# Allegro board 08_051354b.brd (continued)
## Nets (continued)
UNNAMED_12_DIOLED_I181_P: DS4.A(P) R37.1
UNNAMED_12_DIOLED_I182_N: DS5.C Q2.3
UNNAMED_12_DIOLED_I182_P: DS5.A(P) R75.2(N2)
UNNAMED_12_ICFSA642_I1_OEN: R90.2(N2) U7.8
UNNAMED_12_ICFSA642_I1_SEL: S1.2 U7.11
UNNAMED_12_ICPCA9517A_I144_EN: R101.1 U8.5
UNNAMED_12_ICPCA9517A_I145_EN: R24.2(N2) U9.5
UNNAMED_12_RES_I54_N1: R91.1 S1.1(NO)
UNNAMED_12_RES_I55_N2: R36.2(N2) S1.3
UNNAMED_12_RES_I155_N2: R77.2(N2) S3.1
UNNAMED_12_RES_I158_N2: R80.2(N2) S4.2(B)
UNNAMED_12_RES_I178_N2: Q2.2 R78.2(N2)
UNNAMED_12_RES_I179_N2: Q2.5 R79.2(N2)
VD: TP1.1(N1) U4.F1
VL: R10.1 R53.2(N2) R70.2(N2)
VL_AFE: C20.2(N2) C27.1 R10.2(N2) U4.K11(VL)
VLD: P21.2 P21.4 P21.6 P21.8 P21.10 P21.12 P21.14 P21.16 P21.18(N9) P21.20 P21.22 P21.24 R11.1 R39.1 R108.2(N2)
VSUB: C44.1 C55.1 C64.1 JP2.1 JP9.1 R8.2(N2) R56.1 U6.1 U6.8(VDD2)

Pads without a net: P1 11 12 16 17 18 19 20 21 22 23 24 25 26 27 28 29 30; P3 2 3 4 5 8 10 14 15 16 17 20 21 22 23 26 27 28 29 33 35 36 38 39 41 45 47 51 53 57 59 60; P4 3 4 5 6 7 9 11 12 13 14 16 18 20 22 30 31 32 33 34 35 36 37 38; P21 17 19 21 23 25 26 28 41 43 45 47 49 51 53 55 57 59; S2 3; U1 1 7 10 12 25 26 31 32 34 38; U2 B1 C1; U3 6; U4 D4 D5 E5 F6 F7 F8 F9 G6 G7 H6 K5 K9 L2 L3 L9; U5 1; U7 7 24; U10 3 4 8

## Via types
v1: diameter 0.508, hole 0.254, TOP to BOTTOM, 340 vias
v2: diameter 0.254, hole 0.127, TOP to L2_GND, 76 vias
v3: diameter 0.457, hole 0.203, TOP to BOTTOM, 3 vias
v4: diameter 0.254, hole 0.127, L2_GND to L3_SIG, 35 vias
v5: diameter 0.635, hole 0.305, TOP to BOTTOM, 245 vias
v6: diameter 0.254, hole 0.127, L9_GND to BOTTOM, 8 vias

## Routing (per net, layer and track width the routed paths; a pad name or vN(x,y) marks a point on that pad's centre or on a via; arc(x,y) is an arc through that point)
5V_LD: length 1.5
  TOP w0.381: v1(16.9,32.64) 17.09,32.64 17.27,32.82 JP3.1
  vias: v1(36.32,27.18) v1(36.32,26.16) v1(37.34,26.16) v1(38.35,26.16) v1(39.37,27.18) v1(39.37,26.16) v1(50.5,23.44) v1(50.5,22.68) v1(50.47,21.92) v1(50.47,21.16) v5(7.49,23.37) v5(7.49,22.35) v5(7.49,21.34) v5(8.51,21.34) v5(8.64,23.38) v5(9.53,23.38) v5(14.73,31.95) v5(14.69,30.99) v5(14.69,30.1) v5(15.62,31.98)
5VCC: length 15.1
  TOP w0.508: R37.2 v1(38.95,10.29) ; R75.1 v1(42.63,10.25)
  BOTTOM w0.508: JP6.1 v5(31.23,25.76) 32.86,25.76 33.37,25.25 JP8.1 ; v1(5.58,30.86) 5.58,30.81 5.57,30.79 E2.2 5.57,27.14 E3.1 2.62,27.01 C49.2
  BOTTOM w0.584: JP7.1 22.45,23.02
  vias: v1(22.4,19.56) v1(22.43,18.8) v1(23.11,19.56) v1(23.11,18.8) v5(22.02,22.99) v5(22.83,22.99)
9VDD: length 131.2
  TOP w0.127: 77.92,25.43 U4.K10
  TOP w0.305: C15.1 79.72,25.56 79.46,25.83 78.32,25.83 77.92,25.43
  TOP w0.508: R9.1 v5(115.87,21.34) ; v1(82.21,24.28) 82.21,24.65 C12.1 81.22,25.52 80.36,25.52 C15.1
  L8_SIG w0.305: v1(95.83,7.75) v1(95.07,7.75) 92.82,7.75 90.53,10.03 80.14,10.03 77.98,7.87 75.06,7.87 73.53,6.35 61.09,6.35 57.78,3.05 52.83,3.05 47.75,8.13 42.06,8.13 40.26,9.93 40.26,11.62 27.99,23.89 27.99,32.69 29.08,33.78 29.08,41.66 28.32,42.42 15.33,42.42 v1(10.76,37.85)
  BOTTOM w0.203: R26.1 110.81,26.99 110.54,26.72 Q1.4
  BOTTOM w0.254: R26.1 v5(112.27,26.99)
  BOTTOM w0.508: R104.1 v1(10.76,37.85) ; R71.2 v5(93.82,24.38)
GND: length 259
  TOP w0.127: v2(78.45,20.26) 78.15,20.56 77.75,20.56 v2(77.4,20.91)
  TOP w0.165: U4.D6 v2(73.9,23.41)
  TOP w0.203: v5(100.98,11.68) 101.54,11.12 U12.C2
  TOP w0.254: 83.05,38.29 U8.4 ; v1(109.47,22.48) A1.2 A1.PAD ; U4.B7 v2(73.9,23.41) ; 82.29,9.01 C69.1 81.55,9.71 ; P21.42 59.49,20.17 ; P21.38 59.38,21.17 59.46,21.25 ; 59.65,16.09 59.46,16.09 59.39,16.16 P21.58 ; 15.73,38.32 Q2.1 15.12,37.66 ; P21.34 59.47,22.17 ; U4.B3 v2(73.9,21.41) ; C68.2 90.56,42.01 ; 17.03,40.22 Q2.4 17.03,38.9 ; P21.54 59.47,17.17 ; 79.92,15.35 C77.1 79.02,14.47 ; P21.30 59.11,23.17 59.4,23.46 59.4,23.82 v1(59.78,24.2) ; C85.2 41.21,6.33 ; P1.1 48.19,15 ; 69.56,34.43 RT1.1 ; 72.35,4.6 C1.1 ; 82.46,9.27 U13.7 ; C83.1 71.55,30.3 ; U4.E2 v2(74.4,20.91) ; 81.65,42.16 C63.1 80.18,42.16 ; v2(76.9,24.91) U4.H10 v2(75.9,24.91) ; C79.2 104.03,12.89 ; v2(73.4,22.41) U4.C5 ; v2(74.9,24.41) U4.E10 U4.D10 v2(73.9,24.91) U4.C9 v2(73.4,24.41) ; 59.81,18.12 59.46,18.12 59.42,18.17 P21.50 ; P21.46 59.42,19.17 59.46,19.22 59.68,19.22
  TOP w0.305: v5(81.76,38.61) 82.06,38.9 U8.4 ; C23.2 69.39,18.66 v1(69.34,18.61) ; C84.2 v1(39.5,5.71) ; C85.2 v1(40.39,5.71) ; 12.46,43.57 DS3.C ; P21.PAD2 v5(55.05,29.08) P21.PAD1 v5(55.05,32.73) ; 26.14,18.29 25.7,18.29 25.7,18.37 25.39,18.68 U10.19 ; P21.PAD3 v5(55.05,16.76) P21.PAD4 v5(55.05,13.01) ; U10.13 20.87,21.31 ; C26.2 v1(69.35,25.7) ; v1(74.8,16.31) 74.8,16.69 C54.2 ; v1(70.96,16.8) 71.35,16.4 71.82,16.4 C53.1 ; C14.2 70.15,22.59 v1(69.92,22.35) ; C16.2 69.8,20.99 v1(69.39,20.99) ; v1(69.35,19.67) 69.36,19.65 69.37,19.65 69.41,19.62 69.41,19.62 69.48,19.55 C31.2 ; C33.2 v1(76.88,16.36) ; Q2.1 v1(15.73,36.93) ; v1(75.49,16.47) C19.2
  TOP w0.381: U1.20 99.23,19.55 v5(99.49,19.81) ; v5(97.07,25.53) 97.31,25.76 U1.29
  TOP w0.406: U1.6 v5(90.18,23.16) ; v5(99.45,21.21) U1.22 ; Q2.4 v1(18.03,39.56) ; U1.24 99.35,22.51
  TOP w0.508: C57.1 72.91,34.6 v1(72.89,34.62) ; 114.47,26.49 C29.1 v1(115.32,25.76) ; C24.2 v1(62.52,22.41) ; C69.1 v5(80.54,9.01) ; R73.1 71.77,34.42 v1(72.01,34.67) ; C11.2 78.26,29.42 v1(78.25,29.41) ; C11.2 79.17,30.3 ; C11.2 80.07,29.42 ; P1.4 48.35,18 ; C12.2 v1(84.16,25.19) ; C72.2 v5(28.72,25.15) ; C62.1 v5(113.84,20.57) 113.84,19.81 113.2,19.18 C65.2 112.56,18.44 ; v5(21.26,25.02) 21.37,25.03 22.14,25.03 C74.2 ; v5(75.15,6.32) 75.79,6.96 C56.1 ; R18.1 v5(15.01,19.77) ; R57.2 v1(95.63,8.84) ; v5(18.92,34.29) R14.2 19.82,35.07 ; P1.1 46.96,14.36 v5(47.12,14.21) ; C13.2 v1(82.68,34.92) ; C13.2 v1(84.39,33.21) ; C13.2 v1(80.64,33.21) ; JP5.2 107.57,18.54 ; C77.1 79.25,15.12 v1(79.25,14.38) ; Y1.2 62.42,24.89 v5(61.45,24.89) ; U13.7 v5(85.74,9.27) ; P31.3 14.47,9.68 ; P31.3 14.47,13.28 ; P31.3 16.08,11.48 ; P31.3 14.44,11.51 v5(12.78,11.51) ; v5(104.65,12.97) 104.65,12.31 C79.2 103.38,12.33 v5(103.38,12.97) ; C1.1 73.35,4.29 v5(72.27,4.29) ; C1.1 73.66,5.57 ; C1.1 73.66,3.62 ; v5(92.22,12.95) R103.1 91.2,13.67 ; TP18.1 42.18,42.87 v1(42.64,43.32) ; 74.27,35.66 C6.2 74.51,34.92 v1(75.31,34.92) ; C20.1 v1(84.03,26.71) ; R106.1 v5(92.2,9.41) ; 99.45,12.89 C81.2 ; C81.2 v5(100.98,11.68) ; C81.2 v5(97.87,11.68) ; v1(70.35,35.26) 70.35,35.26 70.37,35.23 RT1.1 ; C63.1 v5(80.91,43.37) ; C10.2 67.9,27.6 66.34,29.16 C61.2 v1(64.55,29.64) ; v1(48.35,20.64) 47.99,21 P1.7 ; C5.2 v1(65.31,25.38) ; v1(71.37,30.31) 71.37,29.6 C83.1 ; C68.2 v5(91.96,41.27) ; v5(16.56,6.99) 16.59,7.01 R23.2 ; v1(70.14,14.28) C7.2 ; v5(27.82,34.78) 27.78,34.78 27.36,34.81 R25.2 ; R48.2 v5(32.1,24.51) ; v1(3.29,36.7) R36.1 4.02,35.81 ; v5(48.3,23.31) 48.3,23.49 47.79,24 P1.10 ; A1.PAD v5(111.3,23.58)
  TOP w0.635: DS1.C v1(12.46,34.26) ; DS1.C 12.46,36.97 ; DS1.C 13.62,35.81 ; v1(12.46,41.25) DS3.C 13.62,42.42 ; DS2.C v1(13.72,39.12) ; DS2.C 12.46,40.27 ; DS2.C 12.46,37.96
  TOP w0.762: C82.1 84.02,21.64
  L2_GND w0.14: 74.64,24.83 74.76,24.71 74.76,24.56 v2(74.9,24.41)
  L2_GND w0.203: v1(71.74,22.19) 71.74,22.2
  L9_GND w0.203: v6(23.41,35.68) 23.41,36.53 v1(23.24,36.7)
  BOTTOM w0.203: U7.9 74.25,9.83 v5(74.55,9.53)
  BOTTOM w0.254: R63.1 48.04,15.5 ; 44.19,18.92 U5.4 44.77,17.69 ; 43.19,15.5 R54.1
  BOTTOM w0.305: 16.16,13.41 U3.14 ; U3.5 21.81,13.41 ; U5.4 v5(44.77,20.31) ; U6.5 99.86,15.33 v5(100.23,15.7) 100.59,15.33 U6.4
  BOTTOM w0.381: JP4.3 13.62,10.67 v5(12.78,11.51) ; v5(102.54,34.54) 101.94,33.95 D6.C v5(102.79,33.53) ; U9.4 70.23,33.99 v1(69.39,34.82) ; v5(47.12,14.21) 47.12,14.23 47.27,14.38 R63.1 ; C70.1 v1(66.22,31.99)
  BOTTOM w0.508: P3.30 v5(61.89,8.73) ; C30.2 v5(109.42,30.43) ; R90.1 v5(78.66,10.11) ; R90.1 77.56,9.33 ; R90.1 77.56,10.88 ; v5(47.94,29.91) 47.94,29.19 47.9,29.15 R60.1 48.68,28.44 ; R29.2 v5(106.88,28) ; C40.2 v5(31.1,34.23) ; C40.2 v5(32.43,35.56) ; C40.2 31.1,36.77 ; 39.55,35.49 P4.1 39.55,37.66 39.24,37.97 38.23,37.97 ; P3.6 v5(52.29,8.7) ; v5(30.79,40.64) C35.2 30.01,41.38 ; 77.55,43.45 P4.40 v5(78.7,41.68) ; P3.31 v5(62.69,4.38) ; v5(104.65,12.97) 104.65,12.95 104.41,12.71 C80.2 ; v5(38.38,41.72) 38.43,41.68 P4.2 39.55,43.45 ; P3.55 72.29,4.27 v5(72.27,4.29) ; P3.52 70.69,8.97 70.71,8.99 v5(70.71,9.03) ; P3.24 v5(59.49,8.73) ; C52.2 47.67,24.09 ; R20.2 v5(18.33,6.48) ; v1(50.43,24.3) C67.1 ; C67.1 51.94,23.42 ; C67.1 52.84,24.3 ; 81.41,21.25 R2.1 80.69,22.03 ; P3.43 v5(67.49,4.29) ; C18.2 108.16,24.85 v5(108.4,25.1) ; v5(65.75,8.71) 65.89,8.58 P3.40 ; P3.19 v5(57.89,4.29) ; P3.12 v5(54.69,8.73) ; v5(77.55,35.42) P4.39 78.46,37.42 ; v5(30.01,38.52) R13.2 30.74,39.37 ; v5(73.51,8.72) 73.09,8.31 P3.58 ; JP8.3 v5(36.11,24.13) ; P3.18 v5(57.09,8.73) ; P3.37 v5(65.09,4.29) ; R38.2 103.13,12.72 v5(103.38,12.97) ; R27.2 v5(110.59,30.41) ; P3.13 55.49,3.91 v5(56.22,4.64) ; C75.2 78.76,29.87 ; P3.49 v5(69.89,4.29) ; P3.25 v5(60.29,4.29) ; C42.2 v1(9.86,32.77) ; R54.1 v5(43.96,14.1) ; P3.46 v5(68.29,8.73)
  BOTTOM w0.584: 111.36,29.61 R27.2 ; v5(48.3,23.31) 48.41,23.43 C52.2 ; 105.91,27.27 R29.2 ; 105.15,11.68 C80.2 ; C18.2 107.51,24.15 107.55,24.15 ; C76.2 v5(92.71,22.61)
  vias: v1(48.4,18.67) v1(59.82,14.99) v1(60.25,30.18) v1(60.24,28.14) v1(60.24,26.17) v1(61.34,18.92) v1(61.47,16.89) v1(61.72,22.23) v1(61.72,20.07) v1(61.85,14.99) v1(62.23,20.57) v1(62.61,17.78) v1(69.25,22.58) v1(72.52,28.96) v1(81.55,14.61) v1(82.01,20.77) v1(83.87,21.27) v2(72.57,28.3) v2(73.4,20.91) v2(73.9,20.91) v2(74.4,21.41) v2(74.52,28.38) v2(74.9,21.91) v2(75.9,20.91) v2(76.2,28.3) v2(76.96,28.3) v2(77.9,22.91) v2(79.36,18.08) v2(80.32,27.48) v2(80.31,24.61) v2(80.31,21.32) v5(1.65,25.53) v5(2.54,25.53) v5(3.27,22.42) v5(3.43,25.53) v5(4.25,22.86) v5(4.25,21.97) v5(5.21,23.5) v5(6.22,23.5) v5(10.16,15.62) v5(10.92,16) v5(11.43,6.48) v5(11.43,5.59) v5(11.43,4.7) v5(11.56,15.49) v5(12.19,16) v5(12.78,13.31) v5(12.78,12.45) v5(13.08,3.43) v5(14.1,3.43) v5(15.49,13.36) v5(16.18,4.06) v5(18.03,21.59) v5(18.29,14.86) v5(18.29,13.46) v5(18.92,21.59) v5(18.96,14.16) v5(19.6,14.86) v5(19.56,13.46) v5(21.72,12.19) v5(21.72,11.33) v5(22.99,31.75) v5(22.99,30.86) v5(22.99,29.97) v5(22.99,29.08) v5(22.99,28.19) v5(22.99,27.3) v5(23.88,28.96) v5(24.08,22.15) v5(24.08,21.34) v5(24.08,20.45) v5(24.6,7.18) v5(24.6,5.02) v5(24.77,28.96) v5(24.89,22.15) v5(24.89,21.34) v5(24.89,20.45) v5(25.53,4.06) v5(25.71,22.15) v5(25.71,21.34) v5(25.7,20.45) v5(26.37,4.06) v5(27.18,4.06) v5(27.99,4.06) v5(28.24,16.71) v5(28.24,15.7) v5(28.24,14.68) v5(29.89,16.71) v5(29.89,15.7) v5(40.1,35.57) v5(64.9,14.99) v5(72.14,5.33) v5(100.25,21.97) v5(100.25,16.94) v5(100.88,22.99) v5(101.65,21.34) v5(102.28,22.1) v5(103.12,30.99) v5(103.12,29.97) v5(104.14,30.99) v5(104.14,29.97) v5(106.6,20.73) v5(106.6,19.71) v5(106.6,18.69) v5(106.6,17.68) v5(106.6,16.66) v5(106.6,15.65) v5(107.53,17.73) v6(72.99,25.13) v6(73.67,25.14)
V1: length 19.5
  TOP w0.203: v1(90.1,27.41) 90.1,27.93 90.3,28.13 92.59,28.13 93.21,27.52 U1.37
  L2_GND w0.14: v4(78.53,24.94) 77.43,24.94 v2(76.9,24.41)
  L3_SIG w0.165: v4(78.53,24.94) 78.53,25.3 79.43,26.2 84.53,26.2 84.73,25.99 88.68,25.99 v1(90.1,27.41)
V2: length 16.3
  TOP w0.203: v1(88.1,24.91) 88.63,25.44 89.99,25.44 90.31,25.11 U1.3
  L2_GND w0.14: v2(76.9,23.91) 77.55,24.56 78.66,24.56 v4(79.04,24.94)
  L3_SIG w0.165: v4(79.04,24.94) 79.04,24.9 79.08,24.86 79.08,24.8 79.46,24.42 80.08,24.42 80.92,25.26 83.12,25.26 83.71,24.66 85.93,24.66 86.32,25.05 87.47,25.05 87.61,24.91 v1(88.1,24.91)
V3: length 31.8
  TOP w0.203: v1(93.32,29.66) 93.32,28.23 93.86,27.69 U1.36
  L2_GND w0.14: v1(75,30.2) 74.47,29.67 74.47,28.96 74.93,28.5 74.93,27.2 74.36,26.63 74.36,25.52 75.05,24.84 75.05,24.77 75.53,24.29 75.53,23.73 75.85,23.41 v2(76.4,23.41)
  L3_SIG w0.165: 77.81,32.07 77.79,32.05 77.77,32.05 76.76,31.03 75.84,31.03 v1(75,30.2)
  L3_SIG w0.178: v1(93.32,29.66) 92.69,29.66 90.28,32.07 77.81,32.07
V4: length 14.6
  TOP w0.203: v1(89.49,24.72) 89.75,24.46 U1.4 ; v4(79.55,24.94) 79.17,24.94 79.14,24.91 U4.L10
  L3_SIG w0.165: v1(89.49,24.72) 89.49,25.21 89.18,25.52 84.54,25.52 84.33,25.73 80.34,25.73 v4(79.55,24.94)
V9: length 18
  TOP w0.203: v1(85.3,26.5) 89.8,26.5 90.53,25.76 U1.2
  L3_SIG w0.122: 76.9,23.43 v4(76.9,23.41)
  L3_SIG w0.165: v1(85.3,26.5) 83.63,28.16 80.72,28.16 77.31,24.75 77.31,23.84 76.9,23.43
V10: length 24.2
  TOP w0.203: v1(89.96,18.41) 92.96,18.41 93.21,18.66 U1.13
  L2_GND w0.14: v2(77.4,23.91) 77.67,24.17 v4(78.53,24.17)
  L3_SIG w0.165: v1(89.96,18.41) 91.22,18.41 91.66,18.86 91.66,20.65 90.98,21.33 88.95,21.33 86.61,23.68 80.96,23.68 80.71,23.42 78.82,23.42 78.53,23.71 v4(78.53,24.17)
V11: length 21.6
  TOP w0.203: U1.14 93.86,18.4 93.23,17.78 90.61,17.78 90.58,17.75 v1(90.08,17.75)
  L3_SIG w0.165: v1(90.08,17.75) 89.55,17.75 89.2,18.1 89.2,18.79 85.73,22.26 82.75,22.26 82.45,21.96 78.65,21.96 78.04,22.57 76.56,22.57 v4(76.4,22.41)
V12: length 20.6
  TOP w0.203: v1(94.46,28.08) 94.51,28.03 U1.35 ; v1(87.31,24.35) 86.46,24.35 85.66,23.56 80.14,23.56 79.79,23.91 U4.L8
  BOTTOM w0.203: v1(94.46,28.08) 92.23,28.08 90.59,26.45 88.18,26.45 87.31,25.57 v1(87.31,24.35)
V13: length 16
  TOP w0.203: v1(90.12,22.19) 90.45,21.86 U1.8
  L2_GND w0.14: v4(79.04,24.17) 78.66,23.79 77.78,23.79 v2(77.4,23.41)
  L3_SIG w0.165: v4(79.04,24.17) 79.32,23.89 80.3,23.89 81.2,24.79 82.69,24.79 83.33,24.15 86.8,24.15 88.76,22.19 v1(90.12,22.19)
V14: length 16.2
  TOP w0.203: v1(90.34,19.81) 90.6,19.55 U1.11
  L3_SIG w0.165: v1(90.34,19.81) 89.09,19.81 86.17,22.74 81.66,22.74 81.36,22.43 78.85,22.43 78.37,22.91 v4(76.9,22.91)
V15: length 16
  TOP w0.203: v1(90.31,20.57) 90.31,21.01 90.51,21.21 U1.9
  L2_GND w0.14: v2(77.4,22.91) 77.78,23.29 78.66,23.29 v4(79.04,22.9)
  L3_SIG w0.165: v4(79.04,22.9) 80.93,22.9 81.23,23.21 86.42,23.21 89.05,20.57 v1(90.31,20.57)
V16: length 13.9
  TOP w0.203: U1.5 88.27,23.81 87.5,23.05 80,23.05 79.64,23.41 U4.L7
1P8VDD: length 42.1
  TOP w0.203: 72.51,26.6 72.51,26.3 U4.B11 ; U4.L5 78.27,22.41 ; U4.K1 77.61,20.2 ; U4.A6 72.34,22.91 72.03,23.22 ; 76.4,25.8 U4.H11
  TOP w0.254: U4.B6 U4.A6
  TOP w0.305: C28.1 72.51,27.68 71.69,27.68 ; 78.27,22.41 78.72,21.95 C22.1 80.95,21.95 81.26,21.64 C82.2 ; 76.4,25.8 76.4,26.23 76.96,26.79 v1(76.96,27.1) C17.1 ; U4.E1 74.9,19.3 v1(75.49,18.71) C19.1 ; 77.61,20.2 78.72,19.09 C25.1 78.72,17.3 79.04,16.98 ; U4.B1 73.36,20.36 73.07,20.36 71.37,18.66 71.3,18.66 v1(71.23,18.59) 71.16,18.66 C23.1 ; v1(68.43,22.53) 68.43,22.59 69.05,23.22 C14.1 72.03,23.22
  TOP w0.381: v1(81.23,20.53) 81.25,20.53 81.25,21.57 C82.2 ; 72.51,26.6 C28.1
  TOP w0.508: R72.2 68.44,34.24 v5(68.44,34.51) ; E1.2 66.57,24.36 66.58,24.35 v5(66.58,24.32) ; v1(73.03,31.56) 73.76,31.56 74.27,32.06 C6.1 ; 71.69,27.68 C83.2 70.48,28.88 v1(70.48,29.08) ; C77.2 79.08,17.01 v1(80.02,17.01) ; v5(84.88,17.09) JP1.1
  L3_SIG w0.203: 75.43,20.94 75.63,21.14 75.63,21.14 v4(75.9,21.41)
  L3_SIG w0.305: v1(75.49,18.71) 75.09,19.11 75.09,20.58 75.43,20.92 75.43,20.94
  BOTTOM w0.508: D4.A 92.44,19.43 91.31,18.3 v5(91.31,17.02)
  vias: v5(15.53,22.67) v5(15.58,23.69) v5(16.47,23.69)
2P1VDD: length 1.9
  BOTTOM w0.254: U3.21 18.71,17.64 v1(18.97,17.91)
  vias: v5(17.65,5.21) v5(17.65,4.06) v5(18.67,4.06)
3P3VDD: length 64.9
  TOP w0.203: U4.A10 72.73,24.91 72.54,25.1 72.19,25.1 ; 74.34,19.73 74.4,19.79 U4.D1 ; U4.A4 72.42,21.91 71.92,21.41 ; 72.61,20.62 U4.A2 ; 76.96,26.01 76.9,25.95 U4.J11 ; U4.D11 74.4,25.83 74.76,25.83 74.9,25.69 U4.E11 ; U4.G11 75.9,25.92
  TOP w0.229: 77.21,7.35 E5.1
  TOP w0.254: v1(50.62,28.17) 50.8,28.17 50.8,28.17 P21.9
  TOP w0.305: C68.1 89.13,40.85 U8.8 ; C58.1 v1(76.2,27.1) 76.2,26.79 75.9,26.49 75.9,25.92 ; 72.61,20.62 71.64,19.65 v1(71.23,19.65) ; 74.34,19.73 74.34,18.99 v1(74.6,18.73) ; U4.A8 72.61,23.91 72.42,24.11 72.41,24.11 72.26,24.26 71.69,24.26 v1(71.29,24.66) ; 76.96,26.01 77.85,26.9 77.85,26.92 ; 74.4,25.83 74.25,25.99 74.25,27.03 74.52,27.3 C60.1 74.23,27.74 v1(73.93,28.05) ; C16.1 70.65,20.77 71.13,20.77 71.18,20.72 71.19,20.72 v1(71.21,20.7) 71.92,21.41 ; C26.1 v1(71.21,25.7) 71.58,25.7 72.19,25.1
  TOP w0.381: C31.1 70.62,19.57 71.12,19.57 71.2,19.65 v1(71.23,19.65) ; 77.21,7.35 77.21,6.74 77.29,6.66 v5(77.29,6.64) ; 77.85,26.92 78.27,26.92 C11.1 ; v1(74.6,18.73) 74.6,18.15 C54.1 ; v1(50.62,28.17) v1(49.94,28.17)
  TOP w0.508: C10.1 69.5,29.27 C61.1 69.6,30.1 v1(70.48,30.1) ; v1(70.2,16.96) 70.14,16.91 R65.2 ; v5(85.74,8) 83.96,8 83.95,8.01 C69.2 ; R74.1 91.45,39.12 91.96,39.62 v5(91.96,40.13) R82.1 ; R101.2 v5(91.96,38.1) ; R4.2 67.4,16.41 67.91,16.92 v1(67.91,17.21) ; v1(80.1,30.93) 80.48,31.31 C13.1 ; C11.1 79.17,27.82 79.7,28.35 v1(80.19,28.35) ; v5(89.56,42.29) C68.1 ; v5(4.13,42.28) R91.2
  BOTTOM w0.381: 76.28,31 75.99,31.28 U9.8
  BOTTOM w0.508: R105.2 v5(91.2,8.26) ; R35.1 v1(50.42,25.04) 51.27,25.9 C67.2 ; R93.2 79.6,32.77 79.9,33.06 v5(79.9,33.78) R24.1 ; R94.2 79.59,31.75 80.1,31.24 v1(80.1,30.93) ; 76.28,31 76.59,30.68 C75.1 77.76,30.24 77.69,30.17 77.69,29.91 v1(77.69,29.91) ; R102.2 v5(90.17,12.95)
3P5VDD: length 82.9
  TOP w0.203: U4.C1 73.9,20.18 73.84,20.11
  TOP w0.305: v1(71.55,17.21) 71.55,17.76 71.81,18.02 C53.2 72.28,18.18 72.28,18.57 72.88,19.17 72.9,19.17 73.84,20.11
  TOP w0.508: v1(64.55,13.83) 64.98,13.41 R4.1 ; v5(83.86,14.47) 83.58,14.75 JP1.3 ; R22.2 20.78,1.84 21.03,1.59 29.44,1.59 29.53,1.68 v1(30.19,1.68)
  L8_SIG w0.508: v5(83.86,14.47) 81.97,12.57 79.56,12.57 77.69,14.44 76.81,14.44 76.21,15.04 76.21,16.81 75.88,17.14 71.61,17.14 v1(71.55,17.21)
  BOTTOM w0.508: v1(30.19,1.68) 40.16,1.68 49.66,11.18 52.2,11.18 52.84,10.53 60.59,10.53 63.89,13.83 v1(64.55,13.83) 66.43,13.83 68.69,16.09 68.69,16.44 69.94,17.68 71.08,17.68 v1(71.55,17.21)
AFE_GPO1: length 72.8
  TOP w0.203: v1(70.61,39.24) 69.47,38.1 66.85,38.1 66.47,37.72 61.24,37.72 57.94,41.02 46.35,41.02 44.29,38.95 TP6.1 ; v1(95.12,27.94) 95.5,27.94 95.81,27.64 U1.33
  L2_GND w0.14: v1(76.26,29.29) 75.71,28.74 75.71,26.89 76.25,26.35 76.25,24.76 v2(75.9,24.41)
  L3_SIG w0.165: v1(95.12,27.94) 94.59,27.41 92.04,27.41 89.51,29.94 79.62,29.94 78.58,28.9 76.66,28.9 v1(76.26,29.29)
  L8_SIG w0.165: v1(76.26,29.29) 77.22,30.25 77.22,33.27 76.33,34.16 76.33,36.2 73.28,39.24 v1(70.61,39.24)
AFE_GPO2: length 59.6
  TOP w0.203: v1(40.51,39.37) 40.51,39.02 TP7.1
  L3_SIG w0.165: v1(75.31,34.16) 74.14,33 74.14,30.94 73.3,30.09 73.3,29.44 74.82,27.91 77.22,27.91 77.55,27.58 77.55,26.34 75.9,24.69 v4(75.9,23.91)
  L8_SIG w0.14: v1(40.51,39.37) 41.15,39.37 42.55,37.97 46.61,37.97 46.99,38.35 46.99,40.13 48.51,41.66 58.7,41.66 58.77,41.59 61.76,38.6 67.06,38.6 69.34,36.32 75.06,36.32 75.87,35.51 75.87,34.72 v1(75.31,34.16)
AFE_GPO3: length 119.8
  TOP w0.14: v2(73.45,17.95) 73.45,15.9 73.41,15.85
  TOP w0.203: v1(59.12,11.2) 59.48,10.84 63.53,10.84 64.4,9.97 69.19,9.97 69.53,9.63 72.18,9.63 72.62,10.07 72.62,15.06 v1(72.66,15.1) 73.41,15.85 ; v1(36.67,39.06) TP8.1
  L2_GND w0.14: v2(75.4,21.41) 75.02,21.03 75.02,20.5 74.98,20.46 74.98,20.32 73.75,19.09 73.68,19.09 73.46,18.87 73.46,18.8 73.45,18.79 v2(73.45,17.95)
  L3_SIG w0.165: v1(29.55,25.69) 29.55,25.62 31.22,23.95 32.09,23.95 32.13,23.91 32.15,23.91 43.27,12.79 52.26,12.79 53.85,11.2 58.63,11.2 58.64,11.2 v1(59.12,11.2)
  L8_SIG w0.203: v1(36.67,39.06) 36.67,38.44 33.49,35.27 33.49,29.63 v1(29.55,25.69)
  BOTTOM w0.203: JP9.3 102.45,7.84 102.11,7.49 96.82,7.49 96.05,8.27 92.98,8.27 92.13,7.42 84.26,7.42 80.64,11.03 80.64,14.61 78.26,16.99 74.55,16.99 v1(72.66,15.1) ; v1(29.55,25.69) JP6.3
AFE_GPO4: length 132.7
  TOP w0.203: v1(24.67,25.49) 24.67,26.23 24.18,26.72 23.28,26.72 23.23,26.67 22.74,26.67 22.69,26.72 21.92,26.72 17.12,31.52 17.12,31.53 15.59,33.05 JP3.3 ; TP9.1 35.94,42.14 v1(35.94,41.53)
  L3_SIG w0.165: v4(76.4,21.91) 76.66,22.17 76.68,22.17 76.77,22.26 77.77,22.26 78.53,21.5 82.65,21.5 82.94,21.79 85,21.79 85.22,21.57 85.22,20.36 84.55,19.69 83.54,19.69 83.54,19.68 82.47,19.68 82.27,19.48 82.27,12.46 79.31,9.5 75.41,9.5 72.75,6.84 65.07,6.84 64.23,7.68 v1(64.23,8.74) ; v1(54.04,12.02) 52.72,13.34 43.59,13.34 33.11,23.82 33.11,24.7 31.2,26.61 28.42,26.61 26.6,24.8 24.93,24.8 24.67,25.05 v1(24.67,25.49) 27.46,28.27 31.04,28.27 37.47,34.7 37.47,40.01 v1(35.94,41.53)
  L8_SIG w0.165: v1(64.23,8.74) 64.23,9.74 63.31,10.66 56.21,10.66 54.86,12.02 v1(54.04,12.02)
  BOTTOM w0.203: JP7.3 24.13,24.94 v1(24.67,25.49)
AFE_GPO5: length 62.1
  TOP w0.203: v1(68.64,41.43) 67.27,42.8 61.21,42.8 60.2,41.78 45.37,41.78 TP14.1 ; U4.L4 78.06,21.91 78.21,21.76 78.21,21.76 78.61,21.36 79.41,21.36 80.76,20.01 82.48,20.01 v1(83.13,20.66)
  L8_SIG w0.165: v1(68.64,41.43) 73.3,41.43 82.68,32.05 82.68,25.56 83.78,24.45 83.78,21.89 83.37,21.48 83.37,21.47 83.13,21.23 v1(83.13,20.66)
AFE_GPO6: length 91.4
  TOP w0.203: TP13.1 40.67,41.4 60.58,41.4 61.47,42.29 66.82,42.29 v1(68.58,40.54) ; v2(79.46,19.81) 79.46,19.43 80.32,18.57 85.13,18.57 85.14,18.58 v1(85.74,18.58)
  L2_GND w0.14: v2(77.4,21.91) 77.5,21.91 77.81,21.6 78.26,21.6 78.93,20.94 78.93,20.31 79.42,19.81 v2(79.46,19.81)
  L3_SIG w0.165: v1(85.74,18.58) 87.53,16.79 90.27,16.79 91.17,17.7 93.33,17.7 96.47,14.56 v1(96.47,12.06)
  L8_SIG w0.165: v1(85.74,18.58) 84.34,19.99 83.09,19.99 82.63,20.45 82.63,21.39 82.9,21.67 82.9,21.67 83.15,21.92 83.15,24.32 82.13,25.34 82.13,29.78 78.37,33.54 78.37,35.67 73.51,40.54 v1(68.58,40.54)
  BOTTOM w0.203: JP2.3 v1(96.47,12.06)
AFE_GPO7: length 77.6
  TOP w0.203: LD_EN1.2 49.09,35.53 48.11,36.52 43.6,36.52 43.37,36.75 43.37,39.17 v1(43.73,39.53) 43.94,39.74 43.94,39.9 TP17.1
  L3_SIG w0.165: v1(64.28,39.24) 63.26,39.24 61.46,41.05 44.53,41.05 43.73,40.25 v1(43.73,39.53) ; v1(83.89,20.51) 83.54,20.16 83.34,20.16 83.34,20.15 82.28,20.15 82.13,20.01 80.73,20.01 79.72,21.03 78.52,21.03 77.64,21.91 v4(76.9,21.91)
  L8_SIG w0.165: v1(83.89,20.51) 84.86,21.48 84.86,25.25 83.9,26.21 83.83,26.21 83.15,26.89 83.15,32.24 73.41,41.99 66.95,41.99 64.28,39.32 v1(64.28,39.24)
AFE_GPO8: length 77.6
  TOP w0.203: TP16.1 41.75,39.58 41.95,39.38 v1(42.45,39.38) 42.99,38.85 42.99,36.59 43.44,36.13 47.96,36.13 48.51,35.58 48.51,34.98 49.08,34.42 49.08,34.38 LD_EN2.2 ; v1(81.74,19.25) 80.65,19.25 v2(79.97,19.93)
  L2_GND w0.14: v2(79.97,19.93) 79.97,20.28 80.1,20.4 80.1,20.96 79.15,21.91 77.91,21.91 77.62,22.2 77.61,22.2 77.4,22.41 v2(76.9,22.41)
  L3_SIG w0.165: v1(42.45,39.38) 42.45,40.02 43.95,41.52 62.91,41.52 65.18,39.24 v1(66.62,39.24)
  L8_SIG w0.165: v1(66.62,39.24) 67.38,40.01 73.38,40.01 76.81,36.57 76.81,34.39 78.76,32.45 78.76,20.39 79.63,19.52 81.47,19.52 v1(81.74,19.25)
AFETEMP_I2C1_SCL: length 39.7
  TOP w0.203: v1(86.14,40.44) 86.38,40.2 U8.7 88.97,40.2 89.04,40.13 R82.2 ; 89.04,8 v1(87.39,8)
  BOTTOM w0.203: v1(86.14,40.44) 86.92,39.66 86.92,38.1 86.34,37.51 86.34,24.4 88.69,22.06 88.69,9.3 v1(87.39,8)
AFETEMP_I2C1_SDA: length 36.9
  TOP w0.203: U13.2 v1(87.39,9.27) ; R74.2 88.79,39.12 88.35,39.55 U8.6 86.34,39.55 86.14,39.35 v1(86.14,39.31)
  BOTTOM w0.203: v1(86.14,39.31) 86.14,38.81 86.25,38.7 86.25,38.2 85.82,37.78 85.82,24.29 88.17,21.94 88.17,10.05 v1(87.39,9.27)
CCDGNDA: length 68.5
  TOP w0.203: v1(110.39,17.29) 109.98,17.7 JP5.3 ; v1(73.02,30.6) 73.41,30.21 73.41,27.6 v2(73.58,27.43)
  L2_GND w0.178: v2(74.4,24.41) 74.4,24.56 74.26,24.7 74.26,25.06 73.13,26.18 73.13,26.98 v2(73.58,27.43)
  L3_SIG w0.165: v1(73.02,30.6) 72.52,31.09 72.52,32.81 73.91,34.2 73.91,34.82 75.53,36.44 94.79,36.44 102.54,28.68 105.19,28.68 105.63,28.24 105.63,27.48 105.47,27.32 104.86,27.32 104.69,27.15 104.69,26.82 104.86,26.66 105.47,26.66 105.63,26.49 105.63,26.16 105.47,26 104.86,26 104.69,25.83 104.69,25.5 104.86,25.34 105.47,25.34 105.63,25.17 105.63,24.84 105.47,24.68 104.86,24.68 104.69,24.51 104.69,24.18 104.86,24.02 105.47,24.02 105.63,23.85 105.63,23.52 105.47,23.36 104.86,23.36 104.69,23.19 104.69,22.86 104.86,22.7 105.47,22.7 110.39,17.77 v1(110.39,17.29)
CCDINA: length 68.5
  TOP w0.178: U4.B10 72.78,25.53
  TOP w0.203: v1(111.32,18.17) 110.79,18.17 C21.2 ; 72.78,25.53 72.42,25.53 71.65,26.29 68.34,26.29 v1(68.07,26.56)
  L3_SIG w0.165: v1(68.07,26.56) 68.07,27.68 69.98,29.59 71.84,29.59 72,29.76 72,33.03 73.39,34.41 73.39,35.03 75.31,36.96 95.01,36.96 102.76,29.21 105.41,29.21 106.15,28.46 106.15,22.75 110.75,18.15 111.3,18.15 v1(111.32,18.17)
CLI: length 10.1
  TOP w0.203: R110.2 64.86,23.82 65.07,24.03 v1(65.63,24.03)
  L3_SIG w0.165: v4(73.9,22.91) 73.84,22.91 73.73,23.02 72.42,23.02 72.32,23.12 72.14,23.12 72.13,23.13 70.77,23.13 70.32,23.58 70.32,23.58 70.25,23.64 68.29,23.64 68.17,23.53 66.13,23.53 v1(65.63,24.03)
CLK_N: length 17.5
  L3_SIG w0.127: v1(77.55,12.62) 77.77,12.85 78.25,12.85 78.86,12.24 79.82,12.24 80.78,13.2 80.78,14.91 81.49,15.62 81.49,17.92 80.52,18.89 80.1,18.89 77.67,21.31 77.58,21.31 77,21.31 76.91,21.41 76.91,21.41 v4(76.9,21.41)
  BOTTOM w0.127: U7.2 75.21,12.83 77.34,12.83 v1(77.55,12.62)
CLK_P: length 17.5
  L3_SIG w0.127: v1(77.54,13.4) 77.78,13.16 78.37,13.16 78.98,12.55 79.69,12.55 80.47,13.33 80.47,15.03 81.18,15.74 81.18,17.8 80.4,18.58 79.97,18.58 79.74,18.81 79.48,18.81 79.23,19.06 79.23,19.32 79.02,19.53 78.71,19.53 78.52,19.73 78.52,20.04 78.3,20.25 77.49,20.25 77.33,20.41 77.33,20.57 77.54,20.78 77.54,20.92 77.45,21.01 77,21.01 v4(76.9,20.91)
  BOTTOM w0.127: v1(77.54,13.4) 77.27,13.13 75.18,13.13 U7.1
DATA0_N: length 17.9
  L3_SIG w0.127: v1(74.14,11.82) 74.36,12.04 74.69,12.04 76.08,13.43 76.08,13.87 76.21,14 78.37,14 78.68,14.31 78.68,15.01 78.8,15.14 79.43,15.14 79.8,15.51 79.8,16.25 79.49,16.55 77.86,16.55 77.65,16.77 77.65,17.35 77.77,17.48 78.53,17.48 79,17.94 79,18.65 78.54,19.11 78.12,19.11 76.9,20.32 v4(76.9,20.41)
  BOTTOM w0.127: v1(74.14,11.82) 74.36,12.04 74.7,12.04 74.75,11.99 U7.4
DATA0_P: length 17.9
  L3_SIG w0.127: v4(76.4,20.41) 76.56,20.26 76.56,20.1 76.48,20.02 76.48,19.84 76.6,19.72 76.75,19.72 76.83,19.8 76.99,19.8 77.99,18.8 78.42,18.8 78.69,18.53 78.69,18.07 78.4,17.78 77.65,17.78 77.34,17.48 77.34,16.64 77.73,16.25 79.36,16.25 79.49,16.12 79.49,15.63 79.3,15.45 78.68,15.45 78.37,15.14 78.37,14.43 78.25,14.31 76.08,14.31 75.78,14 75.78,13.56 74.56,12.34 74.36,12.34 v1(74.14,12.56)
  BOTTOM w0.127: U7.3 74.77,12.39 74.73,12.34 74.36,12.34 v1(74.14,12.56)
DATA1_N: length 17.6
  L3_SIG w0.127: v4(76.4,20.91) 76.07,20.58 76.07,19.67 76.36,19.38 76.36,15.46 73.62,12.73 73.62,11.59 73.9,11.31 74.59,11.31 75.78,12.5 76.56,12.5 76.94,12.12 76.94,11.43 76.66,11.15 76.27,11.15 76.06,10.95 v1(76.06,10.92)
  BOTTOM w0.127: U7.6 75.54,11.19 75.58,11.15 75.87,11.15 76.06,10.96 v1(76.06,10.92)
DATA1_P: length 17.7
  L3_SIG w0.127: v4(76.4,21.41) 75.8,20.81 75.8,20.76 75.77,20.73 75.77,19.54 76.06,19.25 76.06,15.59 73.32,12.85 73.32,11.46 73.78,11 74.72,11 75.91,12.19 76.43,12.19 76.63,11.99 76.63,11.61 76.48,11.46 76.26,11.46 v1(76.06,11.65)
  BOTTOM w0.127: U7.5 75.57,11.59 75.71,11.46 75.87,11.46 v1(76.06,11.65)
H1: length 35.5
  TOP w0.203: v1(99.45,25.4) 99.17,25.11 U1.28
  L2_GND w0.14: v2(75.4,24.91) 75.39,24.92 75.39,26.87 75.37,26.89 75.37,28.75 75.36,28.76 v1(75.02,29.1)
  L3_SIG w0.165: v1(75.02,29.1) 75.72,29.8 76.87,29.8 77.48,30.41 77.9,30.41 77.9,30.41 89.99,30.41 91.8,28.6 99.86,28.6 100.35,28.11 100.35,26.29 v1(99.45,25.4)
H2: length 37.8
  TOP w0.203: v1(100.08,25.02) 99.52,24.46 U1.27 ; v1(76,30.32) 76,29.82 75.55,29.37 75.55,27.98 75.4,27.83 U4.F11
  L3_SIG w0.165: 77.97,31.56 76.73,30.32 v1(76,30.32)
  L3_SIG w0.178: v1(100.08,25.02) 100.43,25.37 100.43,25.42 100.99,25.99 100.99,28.39 100.26,29.12 92.25,29.12 89.81,31.56 77.97,31.56
HD: length 59.6
  TOP w0.14: v1(77.09,15.12) 76.04,15.12 75.34,15.82 74.6,15.82 74.6,15.82 74.25,15.82 73.84,16.23 v2(73.84,18.71)
  TOP w0.203: TP2.1 47.99,38.95 48.37,38.95 v1(48.73,39.31)
  L2_GND w0.14: v2(73.84,18.71) 75.4,20.28 v2(75.4,20.91)
  L8_SIG w0.165: v1(48.73,39.31) 57.46,39.31 57.67,39.1 57.7,39.1 60.51,36.29 61.86,36.29 63.54,34.61 63.54,31.66 62.87,30.99 62.87,26.58 63.54,25.91 63.54,23.71 64.18,23.07 64.18,21.18 66.1,19.27 68.62,19.27 68.78,19.11 69.55,19.11 70.75,17.91 76.45,17.91 77.47,16.89 77.47,16.13 77.09,15.75 v1(77.09,15.12)
HL: length 23.4
  L2_GND w0.14: v4(78.66,26.97) 77.89,26.97 76.58,25.66 76.58,24.59 v2(76.4,24.41)
  L3_SIG w0.165: v1(92.45,25.75) 92.45,26.29 89.57,29.17 79.78,29.17 78.66,28.06 v4(78.66,26.97)
  BOTTOM w0.203: v1(92.45,25.75) 92.45,24.96 91.39,23.89 R66.1
I2C2_SCL: length 103.9
  TOP w0.203: v1(43.73,34.12) 44.09,34.48 44.11,34.48 44.29,34.66 TP12.1 ; R98.1 40.34,20.65 40.34,13.89 41.53,12.7 49.4,12.7 52.58,9.53 62.4,9.53 62.69,9.24 v1(62.69,8.73)
  L8_SIG w0.165: v1(43.73,34.12) 43.73,32.27 43.16,31.7 43.16,18.65 44.55,17.26 44.55,13.82 45.94,12.44 50.46,12.44 53.26,9.63 62.48,9.63 62.69,9.42 v1(62.69,8.73)
  BOTTOM w0.203: R41.1 76.3,20.63 76.81,21.13 R43.2 76.94,21.99 77.15,22.19 77.6,22.19 77.81,21.99 77.81,18.47 77.32,17.99 73.25,17.99 70.99,15.73 70.12,15.73 68.2,13.81 68.18,13.81 66.63,12.26 63.93,12.26 63.01,11.34 63,11.34 62.8,11.14 62.8,9.34 62.69,9.24 v1(62.69,8.73) P3.32
I2C2_SDA: length 104.7
  TOP w0.203: TP11.1 46.83,34.7 v1(46.25,34.13) ; R109.1 41.18,20.99 40.78,20.59 40.78,14.46 41.91,13.34 49.53,13.34 52.58,10.29 62.61,10.29 63.49,9.41 v1(63.49,8.73)
  L8_SIG w0.165: v1(63.49,8.73) 63.49,9.53 62.92,10.1 53.46,10.1 50.65,12.91 46.13,12.91 45.02,14.02 45.02,17.45 43.63,18.84 43.63,31.5 v1(46.25,34.13)
  BOTTOM w0.203: R6.1 78.08,23.79 R45.2 78.08,22.27 78.24,22.11 78.24,18.37 77.45,17.57 73.37,17.57 71.15,15.35 70.28,15.35 68.36,13.43 68.34,13.43 66.78,11.88 64.29,11.88 63.32,10.91 63.32,10.07 63.33,10.05 63.33,9.4 63.49,9.24 v1(63.49,8.73) P3.34
IOVDD: length 39.8
  TOP w0.203: U4.G1 75.9,20.14
  TOP w0.305: 75.9,20.14 75.9,19.76 v1(76.88,18.78) C33.1 ; P21.15 50.5,26.67 v1(49.93,26.1)
  TOP w0.381: C63.2 81.55,41.16 81.85,40.85 U8.1
  TOP w0.508: C63.2 v5(79.72,41.16) ; v5(84.82,16.26) JP1.2 ; R80.1 v1(49.3,3.42) ; R87.1 R86.1 80.54,12.44 v1(81.51,13.41) ; R68.2 v5(78.79,39.88) ; R67.2 v5(78.79,38.86) ; R77.1 v1(31.37,4.16)
  L8_SIG w0.381: v1(79.47,20.46) 81.5,22.49 v1(81.5,24.2)
  BOTTOM w0.305: U5.8 46.72,25.42 47.15,25.86 v5(48.41,25.86)
  BOTTOM w0.381: U9.1 v5(68.78,31.28)
  BOTTOM w0.508: v1(81.5,24.2) 80.84,24.2 80.43,23.79 79.76,23.79 79.75,23.8 R45.1 ; R64.2 R61.2 44.34,26.87 v5(44.85,26.37) ; R62.2 46.25,14.83 45.74,14.33 45.59,14.33 ; v1(76.88,18.78) 76.88,19.4 76.94,19.46 R43.1 ; R47.2 45.11,14.81 45.59,14.33 ; v1(66.21,31.2) 66.43,30.99 C70.2 67.76,30.99 68.06,31.28 v5(68.78,31.28) ; 45.59,14.33 v5(45.59,14.25) ; R55.2 46.76,29.25 46.83,29.31 v5(46.83,30.04) ; C52.1 v5(48.41,25.86)
LASERTEMP_I2C1_SCL: length 37.8
  TOP w0.203: P21.5 50.61,29.17 49.28,30.51 49.28,30.76 v1(48.86,31.18)
  BOTTOM w0.203: v1(48.86,31.18) 49.36,30.68 51.89,30.68 55.98,34.78 67.67,34.78 68.67,35.78 70.13,35.78 70.13,35.78 70.56,35.78 70.93,35.42 70.93,34.42 73.42,31.93 U9.7 76.29,31.93 76.47,31.75 R94.1
LASERTEMP_I2C1_SDA: length 45.9
  TOP w0.203: P21.7 50.84,28.67 50.78,28.73 50.42,28.73 48.2,30.95 47.82,30.95 v1(47.46,31.31)
  L3_SIG w0.165: v1(71.61,35.26) 71.08,35.26 69.2,33.37 67.81,33.37 66.58,34.61 66.58,35.13 65.34,36.37 62.52,36.37 61.23,37.66 50.53,37.66 48.13,35.26 48.13,31.98 v1(47.46,31.31)
  BOTTOM w0.203: v1(71.61,35.26) 72.12,35.26 72.13,35.25 73.01,35.25 73.44,34.82 73.44,32.79 73.64,32.58 U9.6 76.54,32.58 76.72,32.77 R93.1
LD1: length 17.4
  TOP w0.178: 71.82,20.57 72.43,21.19 72.68,21.19 U4.A3
  TOP w0.203: P21.60 59.03,15.66 59.06,15.64 v1(60.86,15.64) 62.53,15.64 64.9,18.01 66.83,18.01 69,20.19 69.56,20.19 69.58,20.17 71.42,20.17 71.82,20.57
LD2: length 17.4
  TOP w0.178: U4.A5 72.26,22.41
  TOP w0.203: P21.52 59.26,17.67 59.32,17.61 v1(60.84,17.61) 61.45,17.61 62.51,18.67 64.26,18.67 65.6,20.01 67.18,20.01 68.83,21.66 70.55,21.66 71.12,22.22 71.12,22.41 71.45,22.74 71.94,22.74 72.26,22.41
LD3: length 17.4
  TOP w0.178: 72.02,23.72 72.18,23.72 72.48,23.41 U4.A7
  TOP w0.203: P21.44 60.78,19.67 v1(60.81,19.7) 61.07,19.7 61.32,19.44 61.99,19.44 62.45,19.91 62.74,19.91 63.23,19.42 63.66,19.42 67.41,23.17 68.3,23.17 68.85,23.72 72.02,23.72
LD4: length 17.5
  TOP w0.178: U4.A9 72.74,24.41 72.48,24.68 72,24.68 71.5,25.18 71.12,25.18
  TOP w0.203: P21.36 60.83,21.67 v1(60.86,21.69) 61.75,21.69 62.36,21.08 64.32,21.08 67.21,23.97 68.12,23.97 68.79,24.64 68.79,24.98 68.99,25.18 71.12,25.18
LD5: length 48.9
  TOP w0.14: 73.08,26.83 73.08,26.65 73.08,26.23 U4.C11
  TOP w0.203: v1(72.55,29.88) 73.08,29.36 73.08,26.83
  L8_SIG w0.165: v1(72.55,29.88) 73.42,29.88 75.31,27.99 75.31,22.55 79.19,18.67 81.23,18.67 85.23,14.67 85.23,12.94 85.65,12.52 87.51,12.52 89.33,14.33 92.3,14.33 94.29,16.32 96.82,16.32 99.99,13.16 100.91,13.16 v1(101.09,13.34)
  BOTTOM w0.203: R5.1 101.27,13.16 v1(101.09,13.34)
LD_EN1: length 8
  TOP w0.203: P21.1 51.18,30.18 50.9,30.46 50.6,30.46 50.38,30.67 50.38,31.44 51.2,32.25 51.2,35.04 50.76,35.48 LD_EN1.1
LD_EN2: length 7.3
  TOP w0.203: P21.3 50.84,29.67 50,30.51 50,31.59 50.79,32.38 50.79,34.19 50.62,34.37 LD_EN2.1
LED_BLUE: length 36.5
  TOP w0.203: v1(18.41,35.81) R78.1
  L3_SIG w0.203: v1(18.41,35.81) 20.19,35.81 21.96,37.58 21.96,37.93 22.26,38.24 22.69,38.24 22.85,38.09 24.47,38.09 24.78,38.39 24.78,39.55 25.34,40.12 28.46,40.12 30.5,42.16 36.11,42.16 40.18,38.1 44.28,38.1 v1(45.55,39.37)
  BOTTOM w0.203: P4.8 v1(45.55,39.37)
LED_RED: length 37.5
  TOP w0.203: v1(23.24,38.73) 22.23,38.73 19.68,41.27 R79.1
  L3_SIG w0.203: v1(23.24,38.73) 25.13,40.63 28.25,40.63 30.29,42.67 36.32,42.67 40.39,38.61 43.55,38.61 44.82,39.88 47.1,39.88 v1(47.55,39.43)
  BOTTOM w0.203: P4.10 v1(47.55,39.43)
LS_I2C0_SCL: length 26.9
  L8_SIG w0.165: v1(44.85,31.72) 44.17,31.03 44.17,28.5 44.26,28.41 44.26,28.39 45.69,26.96 v1(45.69,23.52)
  BOTTOM w0.203: v1(45.69,23.52) 45.42,23.79 U5.6 ; P4.15 53.55,34.38 51.81,32.64 45.77,32.64 v1(44.85,31.72) 44.2,31.06 44.2,29.11 44.34,28.96 R61.1
LS_I2C0_SDA: length 30.3
  L8_SIG w0.165: v1(46,31.12) 45.31,31.12 44.68,30.49 44.68,28.71 46.34,27.05 46.34,23.24 45.94,22.84 45.23,22.84 v1(44.55,23.52)
  BOTTOM w0.203: v1(44.55,23.52) 44.77,23.74 U5.5 ; P4.17 55.55,35.36 52.12,31.93 46.8,31.93 v1(46,31.12) 45.47,31.12 44.8,30.45 44.8,29.07 45.44,28.44 R64.1
LS_I2C1_SCL: length 46.7
  TOP w0.203: v1(67.87,32.33) 67.87,33.7 66.64,34.93 66.64,35.88 67.79,37.03 80.44,37.03 80.92,36.55 84.15,36.55 85.09,37.49 85.09,39.78 84.56,40.3 84.05,40.3 83.96,40.2 U8.2 81.1,40.2 R68.1
  L3_SIG w0.165: v1(67.87,32.33) 67.36,32.85 66.92,32.85 65.99,33.78 59.86,33.78 58.23,35.42 v1(57.55,35.42)
  BOTTOM w0.203: P4.19 v1(57.55,35.42) ; U9.2 69.05,31.93 68.65,32.33 v1(67.87,32.33)
LS_I2C1_SDA: length 42.3
  TOP w0.203: R67.1 80.83,38.86 81.52,39.55 U8.3 84.32,39.55 84.71,39.17 84.71,37.65 84.04,36.98 81.05,36.98 80.62,37.41 67.63,37.41 66.26,36.04 66.26,34.74 67.13,33.87 v1(67.13,33.35)
  L3_SIG w0.165: v1(67.13,33.35) 66.21,34.27 60.7,34.27 v1(59.55,35.42)
  BOTTOM w0.203: P4.21 v1(59.55,35.42) ; U9.3 69.22,32.58 68.45,33.35 v1(67.13,33.35)
MIPI_CSI1_CLK_M: length 12.3
  L3_SIG w0.127: v1(71.93,12.23) 71.93,12.23 71.73,12.43 71.23,12.43 70.88,12.79 70.88,13.47 71.3,13.89 72.4,13.89 72.83,13.46 72.83,10.16 72.01,9.34 72.01,8.91 v1(72.3,8.62)
  BOTTOM w0.127: v1(71.93,12.23) 71.94,12.23 72.14,12.43 72.9,12.43 U7.16 ; P3.56 72.07,7.41 72.07,8.39 v1(72.3,8.62)
MIPI_CSI1_CLK_P: length 12.2
  L3_SIG w0.127: v1(71.95,12.94) 71.74,12.74 71.36,12.74 71.18,12.91 71.18,13.35 71.42,13.59 72.27,13.59 72.52,13.34 72.52,11.86 72.4,11.73 72.01,11.73 71.87,11.59 71.87,11.37 72,11.23 72.39,11.23 72.52,11.1 72.52,10.84 72.4,10.71 72.03,10.71 71.9,10.59 71.9,10.35 72.14,10.12 72.14,9.9 71.7,9.46 71.7,8.97 v1(71.37,8.64)
  BOTTOM w0.127: U7.17 72.88,12.73 72.16,12.73 71.95,12.94 v1(71.95,12.94) ; v1(71.37,8.64) 71.7,8.31 71.7,7.4 P3.54
MIPI_CSI1_DATA0_M: length 12.9
  L3_SIG w0.127: v1(67.52,8.7) 67.21,9.01 67.21,9.19 66.25,10.15 66.25,11.31 67.27,12.32 67.72,12.32 67.85,12.19 67.85,12.12 67.98,11.99 68.23,11.99 68.36,12.12 68.36,12.19 68.49,12.32 68.79,12.32 69.12,11.99 69.84,11.99 70.29,11.55 v1(70.35,11.55)
  BOTTOM w0.127: P3.44 67.3,7.39 67.3,8.46 67.52,8.68 v1(67.52,8.7) ; v1(70.35,11.55) 70.57,11.77 71.25,11.77 71.62,11.4 72.33,11.4 72.52,11.59 U7.14
MIPI_CSI1_DATA0_P: length 12.9
  L3_SIG w0.127: v1(66.63,8.7) 66.9,8.98 66.9,9.07 65.95,10.02 65.95,11.43 67.14,12.62 68.92,12.62 69.24,12.3 v1(70.34,12.3)
  BOTTOM w0.127: U7.15 72.49,11.99 72.21,11.71 71.75,11.71 71.38,12.08 70.56,12.08 v1(70.34,12.3) ; P3.42 66.88,7.38 66.88,8.45 v1(66.63,8.7)
MIPI_CSI1_DATA1_M: length 12.5
  L3_SIG w0.127: v1(69.96,8.68) 69.62,9.02 69.62,9.24 69.05,9.82 67.78,9.82 67.31,10.28 67.31,10.73 67.64,11.05 69.02,11.05 69.71,10.36 70.08,10.36 70.21,10.23 70.21,10.09 70.33,9.97 70.59,9.97 70.71,10.09 70.71,10.23 70.84,10.36 71.15,10.36 v1(71.35,10.15)
  BOTTOM w0.127: P3.50 69.7,7.39 69.7,8.42 v1(69.96,8.68) ; v1(71.35,10.15) 71.56,10.36 72.37,10.36 72.63,10.62 U7.12
MIPI_CSI1_DATA1_P: length 12.4
  L3_SIG w0.127: v1(71.33,10.86) 71.13,10.66 69.83,10.66 69.14,11.35 67.51,11.35 67.01,10.85 67.01,10.16 67.65,9.52 68.92,9.52 69.32,9.12 69.32,8.95 v1(69.07,8.7)
  BOTTOM w0.127: v1(71.33,10.86) 71.77,10.86 71.97,10.66 72.24,10.66 72.77,11.19 U7.13 ; P3.48 69.28,7.38 69.28,8.49 v1(69.07,8.7)
REFB: length 6
  L2_GND w0.14: v4(73.9,24.41) v2(74.4,23.91)
  L3_SIG w0.203: v4(73.9,24.41) 73.9,24.52 v3(71.55,26.87)
  BOTTOM w0.203: C8.1 71.88,26.87 v3(71.55,26.87)
REFT: length 4
  L3_SIG w0.203: v4(74.4,23.41) 74.4,23.93 74.3,24.04 74.3,24.74 73.67,25.37 v3(73.67,26.44)
  BOTTOM w0.203: C2.1 v3(73.67,26.44)
RG: length 38
  L3_SIG w0.165: v4(76.4,23.91) 76.4,24.51 78.11,26.21 78.11,27.79 77.5,28.4 75.01,28.4 73.77,29.63 73.77,29.88 76.03,32.14 76.8,32.14 77.24,32.58 90.69,32.58 v1(92.82,30.45)
  BOTTOM w0.203: R69.1 94.6,26.06 95.64,27.1 95.64,28.63 93.82,30.45 v1(92.82,30.45)
RPI_CLKN: length 35.3
  TOP w0.127: v1(48.99,22.12) 48.94,22.12 48.71,22.35 47.32,22.35 P1.8
  L8_SIG w0.127: v1(48.99,22.12) 48.76,22.35 48.35,22.35 48.18,22.19 48.18,21.94 49.47,20.66 58,20.66 59.11,19.56 60.25,19.56 60.86,18.95 60.86,18.72 61.14,18.44 61.9,18.44 62.16,18.69 64.54,18.69 66.62,16.61 69.8,16.61 70.13,16.28 73.73,16.28 74.2,15.8 74.61,15.8 75.09,15.33 v1(75.11,15.33)
  BOTTOM w0.127: U7.23 74.61,13.8 74.61,14.1 74.84,14.33 74.84,15.06 v1(75.11,15.33)
RPI_CLKP: length 35.3
  TOP w0.127: v1(48.97,22.87) 48.93,22.87 48.71,22.66 47.3,22.66 P1.9
  L8_SIG w0.127: v1(48.97,22.87) 48.76,22.66 48.22,22.66 47.88,22.31 47.88,21.82 49.34,20.36 57.88,20.36 58.98,19.25 60.12,19.25 60.55,18.82 60.55,18.6 61.01,18.14 62.03,18.14 62.28,18.39 64.41,18.39 66.5,16.31 69.67,16.31 70.01,15.97 73.6,15.97 v1(74.25,15.32)
  BOTTOM w0.127: U7.22 74.31,13.82 74.31,14.22 74.54,14.45 74.54,15.04 v1(74.25,15.32)
RPI_DATA0N: length 35.2
  TOP w0.127: v1(48.62,16.14) 48.43,16.33 47.83,16.33 47.49,16 P1.2
  L8_SIG w0.127: v1(48.62,16.14) 48.84,16.36 50.66,16.36 51.62,17.31 55.84,17.31 60.79,12.37 63.07,12.37 63.54,12.83 64.89,12.83 65.29,12.43 65.29,11.8 66.17,10.92 68.47,10.92 68.91,11.36 68.91,13.32 69.04,13.45 73.48,13.45 73.81,13.78 73.81,14.42 v1(74.01,14.62)
  BOTTOM w0.127: v1(74.01,14.62) 73.81,14.42 73.81,13.81 U7.21
RPI_DATA0P: length 35.2
  TOP w0.127: v1(48.61,16.89) 48.36,16.64 47.87,16.64 47.51,17 P1.3
  L8_SIG w0.127: v1(73.28,14.59) 73.51,14.36 73.51,13.9 73.36,13.75 68.91,13.75 68.61,13.45 68.61,11.49 68.35,11.23 66.29,11.23 65.6,11.92 65.6,12.56 65.02,13.14 63.41,13.14 62.94,12.67 60.91,12.67 55.97,17.61 51.49,17.61 50.54,16.66 49.86,16.66 49.73,16.79 49.73,16.93 49.6,17.06 49.35,17.06 49.22,16.93 49.22,16.79 49.09,16.66 48.84,16.66 v1(48.61,16.89)
  BOTTOM w0.127: v1(73.28,14.59) 73.51,14.36 73.51,13.82 U7.20
RPI_DATA1N: length 34.7
  TOP w0.127: P1.5 47.49,19 47.84,19.34 48.72,19.34 v1(48.94,19.12)
  L8_SIG w0.127: v1(48.94,19.12) 49.16,19.35 49.47,19.35 49.64,19.18 50.02,19.18 50.18,19.35 50.49,19.35 50.69,19.14 50.99,19.14 51.2,19.35 56.09,19.35 58.17,17.27 59.97,17.27 61.14,16.1 61.79,16.1 62.33,16.64 62.81,16.64 62.93,16.51 62.93,14.28 63.29,13.92 63.89,13.92 64.28,14.32 64.28,15.82 64.41,15.95 65.2,15.95 65.66,15.49 65.66,15.12 65.96,14.81 69.68,14.81 70.08,15.22 71.45,15.22 71.59,15.08 71.59,14.86 v1(71.39,14.66)
  BOTTOM w0.127: U7.18 72.71,13.19 72.64,13.26 72.47,13.26 71.59,14.14 71.59,14.46 v1(71.39,14.66)
RPI_DATA1P: length 34.7
  TOP w0.127: v1(48.93,19.87) 48.71,19.65 47.86,19.65 47.51,20 P1.6
  L8_SIG w0.127: v1(48.93,19.87) 48.94,19.87 49.16,19.65 56.22,19.65 58.29,17.58 60.1,17.58 61.27,16.41 61.67,16.41 62.2,16.94 62.93,16.94 63.24,16.64 63.24,14.41 63.42,14.23 63.76,14.23 63.98,14.45 63.98,15.95 64.28,16.26 65.33,16.26 65.96,15.62 65.96,15.25 66.09,15.12 69.55,15.12 69.96,15.52 71.58,15.52 71.89,15.2 71.89,14.86 v1(72.1,14.66)
  BOTTOM w0.127: U7.19 73.05,13.64 72.97,13.56 72.59,13.56 71.89,14.26 71.89,14.45 v1(72.1,14.66)
RSTB_SYNC: length 62.5
  TOP w0.203: v1(60.66,24.08) 60.66,23.39 60.89,23.16 C24.1 ; v1(46.48,39.24) 46.38,39.24 45.81,38.67 45.81,37.66 46.45,37.02 47.97,37.02 49.05,38.1 58.87,38.1 v1(61.55,35.42) ; TP3.1 46.26,43.43 v1(44.85,43.43)
  L3_SIG w0.122: 75.34,21.4 75.39,21.4 v4(75.9,21.91)
  L3_SIG w0.165: v1(68.28,18.73) 69.03,17.98 71.53,17.98 71.77,18.23 72.17,18.23 75.34,21.4
  L8_SIG w0.165: v1(46.48,39.24) 46.06,39.66 46.06,42.22 v1(44.85,43.43)
  L8_SIG w0.203: v1(68.28,18.73) 65.76,18.73 63.51,20.98 63.51,23.03 62.45,24.08 v1(60.66,24.08) 60.66,24.99 61.55,25.88 v1(61.55,35.42)
  BOTTOM w0.203: P4.23 v1(61.55,35.42)
SPI1_CLK: length 95.5
  TOP w0.203: R113.1 52.86,2.36 50.98,4.25 v1(50.98,9.91) 50.98,10.24 49.18,12.04 41.17,12.04 37.94,15.27 37.94,23.54 41.19,26.79 41.19,32.32 40.03,33.49 38.26,33.49 37.94,33.81 37.94,39.06 TP15.1
  L8_SIG w0.165: v1(60.7,11.78) 63.04,11.78 65.14,9.68 65.14,8.94 63.96,7.75 54.48,7.75 52.32,9.91 v1(50.98,9.91)
  BOTTOM w0.203: R28.1 73.51,20.63 72.51,21.63 71.01,21.63 70.35,20.97 70.35,18.85 69.28,17.78 67.65,17.78 65.7,15.83 64.11,15.83 60.7,12.42 v1(60.7,11.78)
SPI1_CS_N: length 66.9
  TOP w0.203: v1(38.46,37.04) 39.05,37.04 39.21,37.2 TP10.1 ; v1(64.73,11.13) 65.99,12.39 R89.2
  L3_SIG w0.165: v1(64.73,11.13) 63.56,9.96 61.9,9.96 59.81,7.86 55.26,7.86 53.05,5.66 v1(53.05,4.26)
  L8_SIG w0.165: v1(38.46,37.04) 35.31,33.89 35.31,18.29 43.56,10.03 47.27,10.03 v1(53.05,4.26)
  BOTTOM w0.203: P3.7 53.09,4.01 53.05,4.05 v1(53.05,4.26)
SPI1_MISO: length 103.1
  TOP w0.203: TP4.1 41.33,34.83 41.19,34.69 v1(41.19,34.12)
  L3_SIG w0.165: v1(83.88,18.05) 83.63,18.31 83.39,18.31 83.22,18.14 83.22,9.29 81.36,7.43 75.18,7.43 73.62,5.87 72.4,5.87 72.37,5.9 71.9,5.9 71.87,5.87 55.42,5.87 55.16,5.6 v1(55.16,4.77)
  L8_SIG w0.165: v1(55.16,4.77) 54.4,5.53 53.27,5.53 47.79,11.01 43.95,11.01 42.47,12.49 42.47,32.4 41.46,33.41 40.5,33.41 40.22,33.69 40.22,33.93 40.42,34.12 v1(41.19,34.12)
  BOTTOM w0.203: P3.1 50.69,4.31 51.78,5.4 54.95,5.4 55.16,5.2 v1(55.16,4.77) ; v1(83.88,18.05) 84.24,18.41 84.6,18.41 85.09,18.9 85.09,22.68 81.89,25.89 78.14,25.89 77.78,26.25 R88.2
SPI1_MOSI: length 97.8
  TOP w0.203: TP5.1 39.21,34.68 v1(38.65,34.12)
  L3_SIG w0.165: v1(83.85,19.16) 83.47,18.78 83.2,18.78 82.75,18.33 82.75,9.49 81.17,7.9 74.99,7.9 73.43,6.34 72.6,6.34 72.57,6.37 71.71,6.37 71.68,6.34 55.23,6.34 54.45,5.56 v1(54.45,4.77)
  L8_SIG w0.165: v1(54.45,4.77) 54.15,5.06 52.91,5.06 47.43,10.54 43.76,10.54 42,12.3 42,32.2 41.26,32.94 40.31,32.94 39.75,33.5 39.75,33.96 39.58,34.12 v1(38.65,34.12)
  BOTTOM w0.203: R3.1 77.74,25.06 78.09,25.42 81.82,25.42 84.71,22.53 84.71,19.06 84.52,18.87 84.15,18.87 83.86,19.16 v1(83.85,19.16) ; P3.11 54.69,4.01 54.45,4.26 v1(54.45,4.77)
SUB: length 23.6
  TOP w0.203: U1.15 94.51,18.74 v1(94.83,18.41) 95.16,18.74 U1.16
  L3_SIG w0.165: v1(94.83,18.41) 95.14,18.41 v1(104.87,28.14)
  BOTTOM w0.203: D5.C 106.4,29.39 106.01,29 R29.1 105.73,29 v1(104.87,28.14) ; v1(94.83,18.41) 94.53,18.72 D4.C 95.5,19.43 R42.1 C59.2
SUBOUT: length 13.5
  TOP w0.203: U1.18 96.46,18.75 96.79,18.41 97.77,18.41 97.82,18.47 99.95,18.47 103.35,21.87 v1(103.4,21.87)
  BOTTOM w0.203: R7.1 v1(103.4,21.87)
TAL1: length 24.3
  TOP w0.203: v1(59.69,16.64) 59.66,16.66 P21.56
  L3_SIG w0.165: v4(73.9,21.91) 73.9,21.45 73.65,21.2 71.01,21.2 70.86,21.06 70.86,21.06 70.25,20.45 69,20.45 68.62,20.82 68.03,20.82 67.4,20.19 66.8,20.19 66.63,20.36 66.63,21.29 66.9,21.57 v1(67.39,21.57)
  BOTTOM w0.203: v1(67.39,21.57) 67.69,21.27 67.69,18.92 66.23,17.46 63.18,17.46 61.95,16.23 61.18,16.23 60.78,16.64 v1(59.69,16.64)
TAL2: length 24.2
  TOP w0.203: P21.48 59.69,18.67 v1(59.69,18.67)
  L3_SIG w0.165: v4(73.4,21.91) 73.4,21.71 73.24,21.55 73,21.55 72.88,21.67 70.81,21.67 70.6,21.46 69.71,21.46 69.08,22.1 68.77,22.1 68.61,21.93 68.61,21.72 68.42,21.53 68.08,21.53 67.53,20.98 67.41,20.98 v1(67.14,20.71)
  BOTTOM w0.203: v1(59.69,18.67) 60.1,18.26 60.22,18.26 60.22,18.25 61.75,18.25 61.95,18.46 61.95,19.36 62.13,19.54 62.39,19.54 62.56,19.36 62.56,18.7 62.74,18.52 63,18.52 63.17,18.7 63.17,19.36 63.35,19.54 63.61,19.54 63.78,19.36 63.78,18.7 63.96,18.52 64.21,18.52 64.39,18.7 64.39,19.36 64.57,19.54 64.82,19.54 65,19.36 65,18.62 65.21,18.41 66.1,18.41 66.41,18.72 66.41,20.51 66.61,20.71 v1(67.14,20.71)
TAL3: length 24.3
  TOP w0.203: P21.40 59.66,20.67 v1(59.69,20.7)
  L3_SIG w0.165: v1(69.68,24.63) 70.6,24.63 71.09,24.15 71.51,24.15 71.99,24.63 72.3,24.63 72.64,24.3 72.64,24.17 72.89,23.91 v4(73.4,23.91)
  BOTTOM w0.203: v1(59.69,20.7) 59.73,20.7 59.97,20.46 61.13,20.46 62.05,21.39 62.05,21.64 62.26,21.84 62.66,21.84 62.87,21.64 62.87,20.65 63.07,20.45 63.47,20.45 63.68,20.65 63.68,21.64 63.88,21.84 64.29,21.84 64.49,21.64 64.49,20.65 64.69,20.45 65.07,20.45 65.28,20.65 65.28,21.46 65.66,21.84 66.14,21.84 68.11,23.82 68.77,23.82 69.19,23.39 69.85,23.39 70.06,23.59 70.06,24.26 v1(69.68,24.63)
TAL4: length 24.3
  TOP w0.203: v1(59.69,22.73) 59.63,22.67 P21.32
  L3_SIG w0.165: v1(67.75,24.57) 67.88,24.57 67.9,24.58 68.68,24.58 69.29,25.2 69.7,25.2 69.96,25.46 70.62,25.46 70.89,25.2 72.61,25.2 v4(73.9,23.91)
  BOTTOM w0.203: v1(59.69,22.73) 60.63,22.73 61.35,23.45 61.35,23.92 61.54,24.11 61.79,24.11 61.97,23.93 61.97,23.16 62.15,22.98 62.4,22.98 62.59,23.17 62.59,24.23 62.77,24.41 63.02,24.41 63.19,24.24 63.19,23.16 63.37,22.98 63.62,22.98 63.83,23.19 63.83,24.22 64,24.39 64.25,24.39 64.4,24.24 64.4,23.19 64.61,22.99 66.17,22.99 v1(67.75,24.57)
TAL5: length 51.9
  L3_SIG w0.165: v4(74.9,23.91) 74.68,24.13 74.68,24.97 74.27,25.37 74.27,26.62 73.94,26.95 72.61,26.95 72.1,27.47 71.21,27.47 70.36,26.62 69.01,26.62 v1(68.07,25.68)
  L8_SIG w0.165: v1(96.89,15.24) 96.37,15.76 94.44,15.76 92.51,13.83 89.54,13.83 87.72,12.01 85.49,12.01 84.76,12.74 84.76,14.46 83.15,16.07 79.94,16.07 79.34,16.67 79.34,17.85 73.95,23.24 69.93,23.24 68.07,25.1 v1(68.07,25.68)
  BOTTOM w0.203: R42.2 95.89,18.03 R40.1 95.89,16.24 v1(96.89,15.24)
TAVDD: length 21.9
  TOP w0.508: v1(67.98,14.33) 68.51,14.33 69.13,14.9 C7.1 R65.1
  L3_SIG w0.127: v4(74.9,22.91) 74.57,22.58 73.22,22.58 73.13,22.67 71.95,22.67 71.94,22.68 70.59,22.68 70.13,23.13 70.1,23.13 70.06,23.17
  L3_SIG w0.165: v1(67.98,14.33) 67.9,14.33 65.28,16.96 65.28,21.84 66.5,23.06 68.37,23.06 68.48,23.17 70.06,23.17
TEMP_CT_AFE: length 58.1
  TOP w0.203: v1(87.5,14.45) 87.5,12.85 85.19,10.54 U13.6 R87.2
  L8_SIG w0.165: v1(87.5,14.45) 86.9,15.05 86.9,24.05 86.72,24.23 86.72,30.09 73.76,43.05 64.72,43.05 v1(61.55,39.89)
  BOTTOM w0.203: P4.24 v1(61.55,39.89)
TEMP_CT_LASER: length 28
  TOP w0.203: v1(49.06,29.31) 49.06,28.31 49.72,27.65 50.81,27.65 50.84,27.67 P21.11
  L3_SIG w0.165: v1(49.06,29.31) 49.76,29.31 50.69,30.25 50.69,35.77 51.99,37.06 60.81,37.06 62.45,35.42 v1(63.55,35.42)
  BOTTOM w0.203: P4.25 v1(63.55,35.42)
TEMP_INT_AFE: length 53.2
  TOP w0.203: v1(86.43,14.28) 86.43,12.9 85.34,11.81 U13.5 R86.2
  L8_SIG w0.165: v1(63.55,39.89) 66.18,42.51 73.64,42.51 86.21,29.94 86.21,24.08 86.43,23.86 v1(86.43,14.28)
  BOTTOM w0.203: P4.26 v1(63.55,39.89)
TEMP_INT_LASER: length 28.2
  TOP w0.203: v1(50.13,27.11) 50.64,27.11 50.7,27.17 P21.13
  L3_SIG w0.165: v1(65.55,35.42) 64.92,34.78 61.48,34.78 60.25,36.02 52.35,36.02 51.69,35.36 51.69,28.29 50.92,27.53 50.92,27.41 50.62,27.11 v1(50.13,27.11)
  BOTTOM w0.203: P4.27 v1(65.55,35.42)
UNNAMED_5_ADP2505V2_I467_BSTA: length 3.1
  BOTTOM w0.254: C36.2 21.08,38.27 21.08,37.52 U2.A1
UNNAMED_5_ADP2505V2_I467_BSTB: length 3.9
  BOTTOM w0.254: U2.E2 24.89,35.68 25.65,36.45 25.65,38.24 C37.1
UNNAMED_5_ADP2505V2_I467_CM: length 9.6
  TOP w0.203: v1(28.24,39.37) 25.02,39.37 v1(24.26,38.61)
  BOTTOM w0.203: v1(28.24,39.37) R13.1 C35.1 ; v1(24.26,38.61) 24.26,38.1 25.09,37.27 25.09,36.46 24.81,36.18 U2.E1
UNNAMED_5_ADP2505V2_I467_EN: length 11.7
  TOP w0.203: JP3.2 16.43,34.87 16.61,35.05 17.91,35.05 18.34,34.62 18.34,34.05 18.99,33.4 21.84,33.4 v1(22.1,33.66) 22.1,34.09 21.89,34.29 R14.1
  L9_GND w0.203: v6(23.41,35.18) 23.41,34.97 v1(22.1,33.66)
UNNAMED_5_ADP2505V2_I467_FB: length 4.4
  TOP w0.203: v1(24.51,36.83) 25.53,36.83 25.83,36.53 R12.2 R25.1
  BOTTOM w0.203: v1(24.51,36.83) 24.12,36.83 23.92,36.63 U2.D1
UNNAMED_5_ADP2505V2_I467_PGN: length 11.7
  TOP w0.203: v1(30.75,37.59) 29.26,37.59 28.88,37.97 22.73,37.97 v1(22.48,37.72)
  L9_GND w0.203: v1(22.48,37.72) 22.23,37.47 22.23,36.96 22.91,36.27 v6(22.91,35.68)
  BOTTOM w0.203: R15.1 v1(30.75,37.59)
UNNAMED_5_ADP2505V2_I467_SWA1: length 1.5
  L9_GND w0.203: v6(22.41,35.68) 22.41,35.5 22.73,35.18 v6(22.91,35.18)
  BOTTOM w0.203: 21.75,35.71 21.78,35.68 v6(22.41,35.68)
UNNAMED_5_ADP2505V2_I467_SWB1: length 0.9
  BOTTOM w0.203: U2.D3 U2.E3 24.43,35.19 24.82,35.19
UNNAMED_5_ADP2505V2_I467_VDR: length 14.1
  TOP w0.203: v1(28.11,35.56) 28.47,35.2 28.47,34.22 28.23,33.98 24.36,33.98 23.92,34.42 v1(23.92,37.34)
  L9_GND w0.203: v1(23.92,37.34) v6(23.92,35.68)
  BOTTOM w0.203: C40.1 v1(28.11,35.56)
  BOTTOM w0.381: R15.2 29.01,36.83 29.19,36.65 C40.1
UNNAMED_5_ADP2505V2_I467_VOUT1: length 0.9
  TOP w0.203: v1(25.02,34.54) 25.39,34.54 25.66,34.81 R12.1
UNNAMED_5_ADP5023_I567_AVIN: length 7.4
  BOTTOM w0.203: U3.12 16.65,12.16 v5(16.56,12.06)
  BOTTOM w0.254: v1(19.43,17.14) 19.21,16.92 U3.22
  BOTTOM w0.305: U3.7 v5(20.87,12.16) ; U3.17 16.34,14.91 16,15.24 ; U3.3 21.92,14.41 ; 16.06,14.41 U3.16
  BOTTOM w0.381: v5(16.56,12.06) 16.25,11.76 JP4.1
  vias: v5(15.49,14.61) v5(15.75,15.88) v5(22.43,17.9) v5(23.24,17.95)
